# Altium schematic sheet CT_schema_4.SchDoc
size 297 x 271 mm
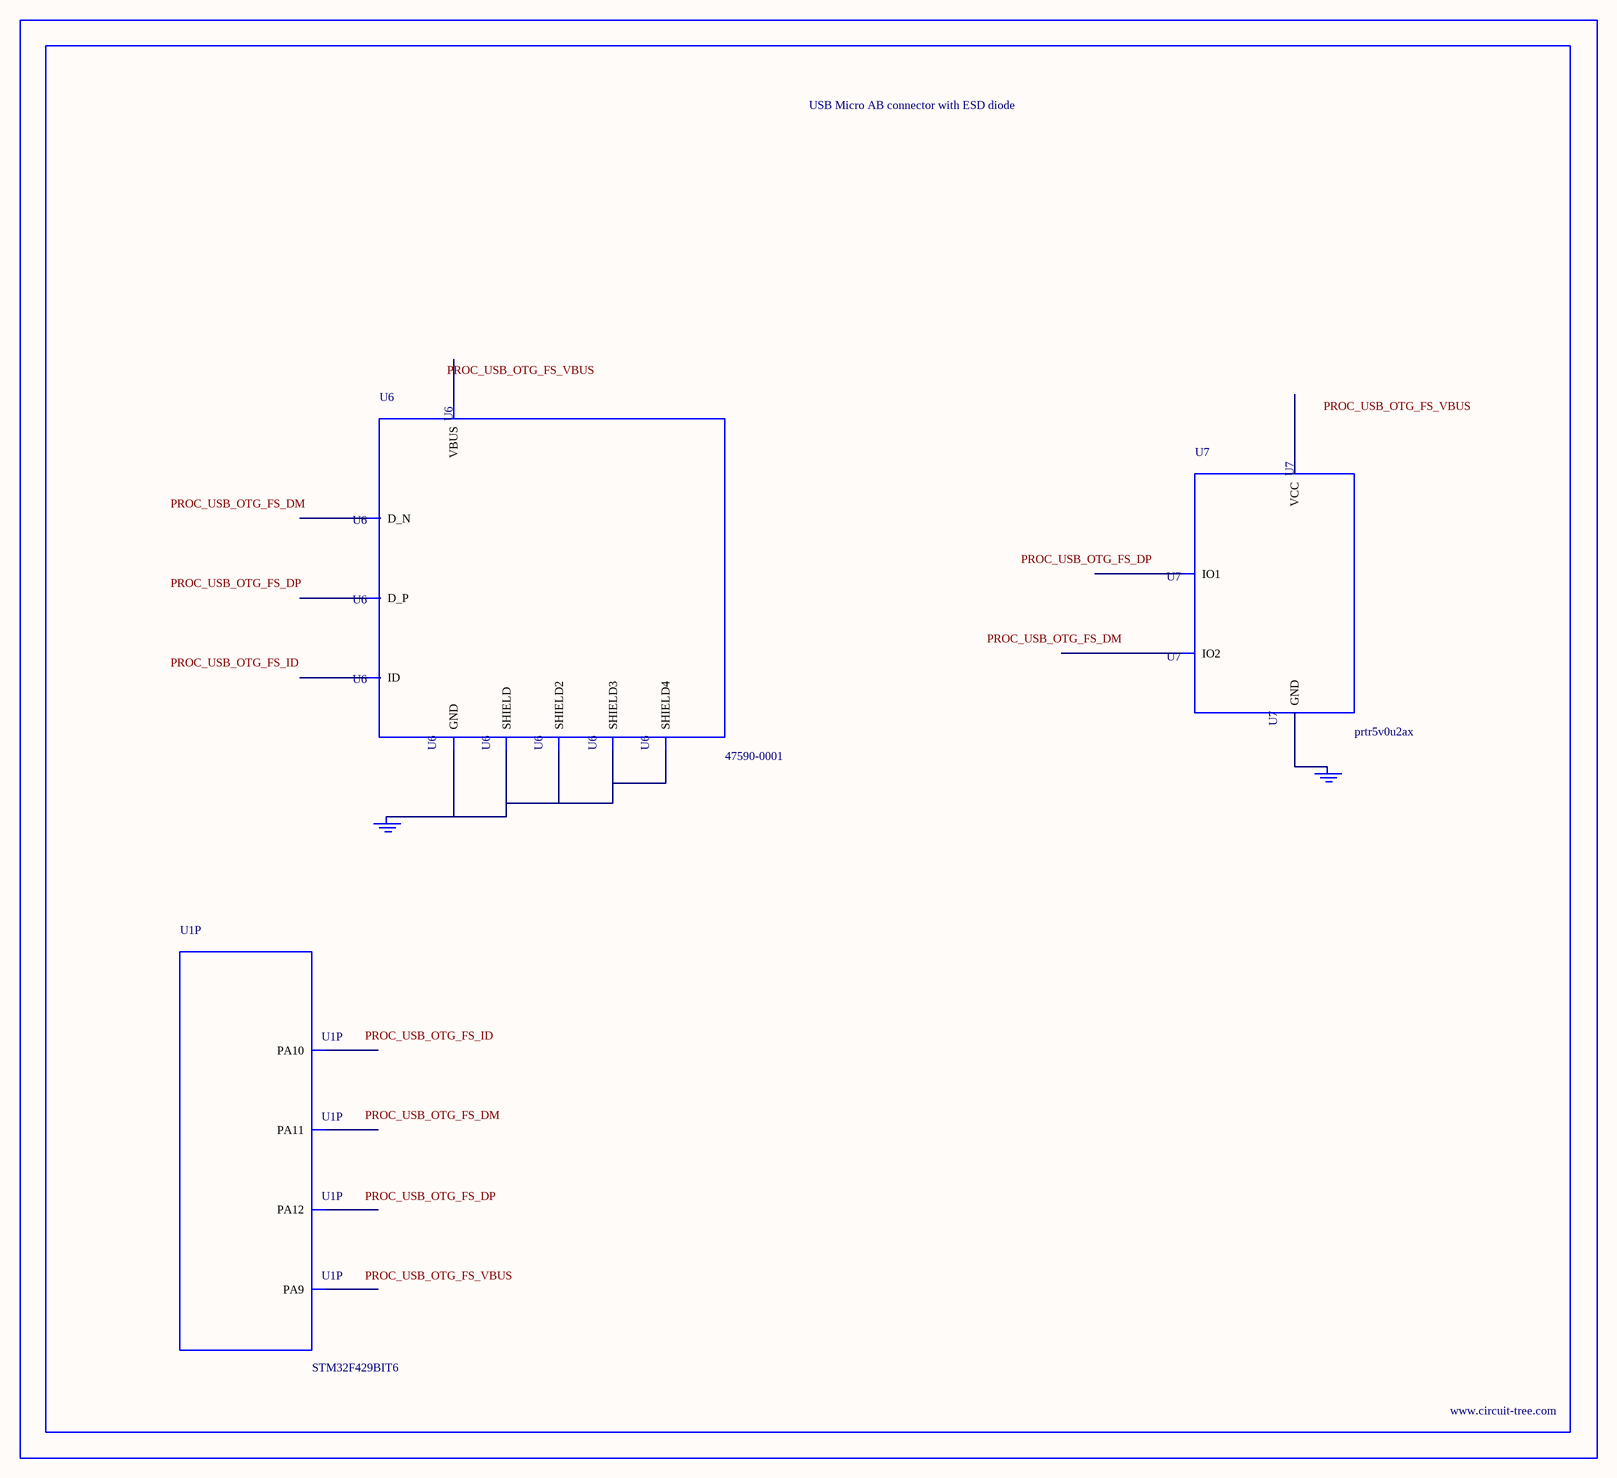
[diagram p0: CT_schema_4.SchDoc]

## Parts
BORDER3  (no value)
GND_INSTANCE_3_0  (no value)
GND_INSTANCE_3_1  (no value)
U1  STM32F429BIT6  [LQFP208]  (part P of 16)
U6  47590-0001  [MICRO_USB_AB]
U7  prtr5v0u2ax  [SOT143B]

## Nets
NetGND_INSTANCE_3_0_0: GND_INSTANCE_3_0.0(GND) U6.5(GND) U6.6(SHIELD) U6.7(SHIELD2) U6.8(SHIELD3) U6.9(SHIELD4)
NetGND_INSTANCE_3_1_0: GND_INSTANCE_3_1.0(GND) U7.1(GND)

Not connected (* = marked no-connect by the designer): U1 143(PA9) 144(PA10) 145(PA11) 146(PA12); U6 1(VBUS) 2(D_N) 3(D_P) 4(ID); U7 2(IO1) 3(IO2) 4(VCC)

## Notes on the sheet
- Labels drawn without touching a wire or pin: PROC_USB_OTG_FS_DM, PROC_USB_OTG_FS_DP, PROC_USB_OTG_FS_ID, PROC_USB_OTG_FS_VBUS

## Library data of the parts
BORDER3 = BORDER_PAGE3
GND_INSTANCE_3_0 GND_INSTANCE_3_1 = GND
